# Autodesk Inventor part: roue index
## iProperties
Author: Administrateur
Shininess: 20.0
PropertySet Name: _Private Model Information
Length Units: 11269
Angle Units: 11283
Time Units: 11279
Mass Units: 11290
Length Display Precision: 3
Angle Display Precision: 2
Compacted: False
Created: 2001-04
Part Number: roue index
Material: Par défaut
Document SubType Name: Modélisation
Designer: Administrateur
Control State: 0
Master: False
Checked Out: False
PropertySet Name: Design Tracking Control
Density: 0.0
Volumn: 0.0
Area: 0.0
PropertySet Name: Model Information
